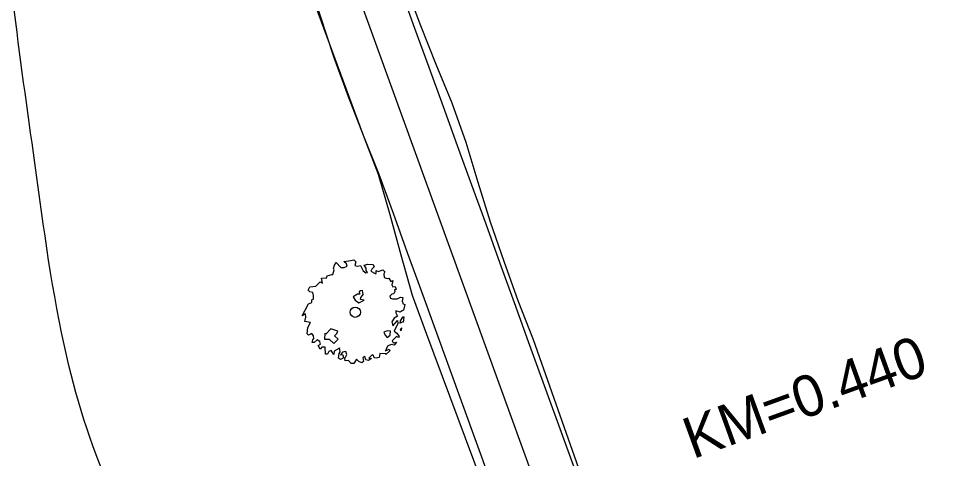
# Model space of a CAD drawing. Extents: x -475575 to -473225, y -1116053 to -1114104.
# Drawn here: x -474215.18 to -474170.87, y -1115076.88 to -1115055.77 of the extents above; entities that cross this region are included whole.
import ezdxf

# ---------------------------------------------------------------- set-up
doc = ezdxf.new("R2010")
doc.units = 0
for name, color, linetype in [('CESTN___P____KOP_N__VRH', 7, 'Continuous'), ('CESTN___P____KOP_N__VRH__Construction_', 7, 'Continuous'), ('IP', 7, 'Continuous'), ('POLYGONY_SITUACE_PF_POPISY', 7, 'Continuous'), ('POLYGONY_SITUACE_PO', 7, 'Continuous'), ('Vrstevnice_vedlejsi', 7, 'Continuous')]:
    doc.layers.add(name, color=color, linetype=linetype)

msp = doc.modelspace()

# ---------------------------------------------------------------- linework, layer by layer
at = {"layer": 'CESTN___P____KOP_N__VRH'}
msp.add_lwpolyline([(-474214.371, -1115044.57), (-474211.961, -1115044.624), (-474209.401, -1115045.159), (-474206.197, -1115046.957), (-474204.043, -1115049), (-474202.628, -1115051.043), (-474201.908, -1115052.531), (-474198.644, -1115061.375)], dxfattribs=at)
at = {"layer": 'CESTN___P____KOP_N__VRH__Construction_'}
for p, q in [((-474199.594, -1115046.827), (-474196.185, -1115056.228)), ((-474195.889, -1115056.121), (-474199.382, -1115046.751)), ((-474195.147, -1115057.979), (-474195.889, -1115056.121)), ((-474196.185, -1115056.228), (-474195.503, -1115058.108)), ((-474200.065, -1115057.635), (-474199.368, -1115059.51)), ((-474195.503, -1115058.108), (-474194.821, -1115059.989)), ((-474194.377, -1115059.828), (-474195.147, -1115057.979)), ((-474199.368, -1115059.51), (-474198.644, -1115061.375)), ((-474194.821, -1115059.989), (-474194.139, -1115061.869)), ((-474193.717, -1115061.716), (-474194.377, -1115059.828)), ((-474198.644, -1115061.375), (-474197.9, -1115063.232)), ((-474198.644, -1115061.375), (-474197.93, -1115063.243)), ((-474194.139, -1115061.869), (-474193.458, -1115063.749)), ((-474193.138, -1115063.633), (-474193.717, -1115061.716)), ((-474197.93, -1115063.243), (-474197.377, -1115065.17)), ((-474197.9, -1115063.232), (-474197.218, -1115065.113)), ((-474192.541, -1115065.544), (-474193.138, -1115063.633)), ((-474193.458, -1115063.749), (-474192.776, -1115065.629)), ((-474197.377, -1115065.17), (-474196.84, -1115067.103)), ((-474197.218, -1115065.113), (-474196.536, -1115066.993)), ((-474192.776, -1115065.629), (-474192.094, -1115067.509)), ((-474191.883, -1115067.433), (-474192.541, -1115065.544)), ((-474196.84, -1115067.103), (-474196.308, -1115069.037)), ((-474196.536, -1115066.993), (-474195.854, -1115068.873)), ((-474192.094, -1115067.509), (-474191.412, -1115069.39)), ((-474191.215, -1115069.318), (-474191.883, -1115067.433)), ((-474195.854, -1115068.873), (-474184.886, -1115099.122)), ((-474196.308, -1115069.037), (-474195.612, -1115070.912)), ((-474191.412, -1115069.39), (-474190.731, -1115071.27)), ((-474190.479, -1115071.179), (-474191.215, -1115069.318)), ((-474195.612, -1115070.912), (-474185.046, -1115099.18)), ((-474181.118, -1115097.755), (-474190.479, -1115071.179)), ((-474190.731, -1115071.27), (-474181.126, -1115097.758))]:
    msp.add_line(p, q, dxfattribs=at)
msp.add_lwpolyline([(-474203.734, -1115048.833), (-474202.08, -1115051.439), (-474200.065, -1115057.635)], dxfattribs=at)
at = {"layer": 'IP'}
for points in [[(-474197.058, -1115071.292), (-474197.172, -1115071.441), (-474197.301, -1115071.406), (-474197.477, -1115071.497), (-474197.573, -1115071.707), (-474197.402, -1115071.64), (-474197.378, -1115071.719), (-474197.571, -1115071.898), (-474197.56, -1115071.863), (-474197.856, -1115071.849), (-474197.876, -1115072.031), (-474198.006, -1115072.07), (-474198.124, -1115072.047), (-474198.148, -1115071.943), (-474198.219, -1115071.914), (-474198.372, -1115072.065), (-474198.248, -1115072.086), (-474198.391, -1115072.179), (-474198.525, -1115072.143), (-474198.575, -1115071.99), (-474198.669, -1115072.037), (-474198.627, -1115072.23), (-474198.72, -1115072.284), (-474198.857, -1115072.225), (-474198.97, -1115072.108), (-474199.099, -1115072.32), (-474199.221, -1115072.316), (-474199.351, -1115072.174), (-474199.506, -1115072.189), (-474199.529, -1115072.081), (-474199.438, -1115071.89), (-474199.487, -1115071.746), (-474199.646, -1115071.771), (-474199.73, -1115071.907), (-474199.646, -1115071.896), (-474199.608, -1115071.964), (-474199.59, -1115072.054), (-474199.743, -1115072.126), (-474199.832, -1115072.061), (-474199.802, -1115071.836), (-474199.751, -1115071.758), (-474199.778, -1115071.567), (-474199.786, -1115071.587), (-474200.035, -1115071.728), (-474200.056, -1115071.891), (-474200.179, -1115071.703), (-474200.3, -1115071.74), (-474200.356, -1115071.874), (-474200.454, -1115071.871), (-474200.47, -1115071.545), (-474200.63, -1115071.538), (-474200.707, -1115071.628), (-474200.801, -1115071.465), (-474200.7, -1115071.397), (-474200.732, -1115071.26), (-474200.855, -1115071.179), (-474201.003, -1115071.321), (-474201.09, -1115071.322), (-474201.07, -1115071.187), (-474201.024, -1115071.117), (-474201.029, -1115070.996), (-474201.112, -1115070.889), (-474201.271, -1115070.965), (-474201.332, -1115070.9), (-474201.299, -1115070.59), (-474201.177, -1115070.361), (-474201.447, -1115070.301), (-474201.392, -1115070.093), (-474201.409, -1115069.947), (-474201.577, -1115070.04), (-474201.278, -1115069.463), (-474201.116, -1115069.393), (-474201.11, -1115069.264), (-474201.035, -1115069.236), (-474201.031, -1115069.056), (-474201.058, -1115068.919), (-474201.215, -1115068.889), (-474201.285, -1115068.802), (-474201.205, -1115068.647), (-474200.921, -1115068.615), (-474200.719, -1115068.407), (-474200.608, -1115068.467), (-474200.652, -1115068.222), (-474200.407, -1115068.206), (-474200.38, -1115068.117), (-474200.156, -1115068.054), (-474200.103, -1115068.055), (-474200.04, -1115067.824), (-474200.078, -1115067.758), (-474200.02, -1115067.6), (-474199.939, -1115067.473), (-474199.729, -1115067.709), (-474199.563, -1115067.716), (-474199.42, -1115067.648), (-474199.455, -1115067.539), (-474199.583, -1115067.432), (-474199.344, -1115067.401), (-474199.097, -1115067.342), (-474199.01, -1115067.439), (-474199.051, -1115067.628), (-474198.928, -1115067.647), (-474198.777, -1115067.615), (-474198.644, -1115067.872), (-474198.529, -1115067.97), (-474198.435, -1115067.953), (-474198.512, -1115067.855), (-474198.512, -1115067.741), (-474198.596, -1115067.606), (-474198.422, -1115067.552), (-474198.169, -1115067.567), (-474198.121, -1115067.687), (-474198.241, -1115067.789), (-474198.281, -1115067.898), (-474198.071, -1115068.001), (-474198.035, -1115068.011), (-474198.033, -1115067.856), (-474197.915, -1115067.914), (-474197.842, -1115067.87), (-474197.712, -1115067.827), (-474197.61, -1115067.917), (-474197.654, -1115068.02), (-474197.637, -1115068.198), (-474197.498, -1115068.243), (-474197.412, -1115068.225), (-474197.325, -1115068.383), (-474197.231, -1115068.342), (-474197.274, -1115068.547), (-474197.222, -1115068.639), (-474197.118, -1115068.634), (-474197.073, -1115068.769), (-474197.143, -1115068.783), (-474197.137, -1115068.865), (-474197.163, -1115068.952), (-474197.201, -1115068.986), (-474197.268, -1115069.001), (-474197.327, -1115069.044), (-474197.369, -1115069.098), (-474197.345, -1115069.181), (-474197.246, -1115069.217), (-474197.025, -1115069.218), (-474196.855, -1115069.145), (-474196.75, -1115069.154), (-474196.781, -1115069.336), (-474196.736, -1115069.466), (-474196.658, -1115069.497), (-474196.719, -1115069.769), (-474196.787, -1115069.792), (-474196.883, -1115069.854), (-474197.08, -1115069.799), (-474197.088, -1115069.897), (-474197, -1115070.053), (-474197.158, -1115070.151), (-474197.268, -1115070.316), (-474197.225, -1115070.519), (-474197.002, -1115070.264), (-474196.99, -1115070.4), (-474197.167, -1115070.777), (-474197.032, -1115070.859), (-474196.932, -1115071.028), (-474196.952, -1115071.073), (-474197.056, -1115071.025), (-474197.26, -1115071.233), (-474197.216, -1115071.329)], [(-474198.787, -1115069), (-474198.93, -1115069), (-474199.131, -1115069.129), (-474199.035, -1115069.28), (-474198.86, -1115069.408), (-474198.6, -1115069.285), (-474198.776, -1115069.255), (-474198.758, -1115069.152), (-474198.688, -1115069.056), (-474198.658, -1115069.015), (-474198.68, -1115068.827), (-474198.774, -1115068.838), (-474198.85, -1115068.889), (-474198.821, -1115068.961)], [(-474196.767, -1115070.094), (-474196.879, -1115070.271), (-474196.894, -1115070.386), (-474196.74, -1115070.312), (-474196.716, -1115070.344), (-474196.681, -1115070.096)], [(-474199.871, -1115070.768), (-474200.199, -1115070.655), (-474200.44, -1115070.915), (-474200.493, -1115070.866), (-474200.5, -1115071.156), (-474200.28, -1115071.161), (-474200.058, -1115071.37), (-474199.849, -1115071.148), (-474200.019, -1115070.989), (-474199.921, -1115070.885)], [(-474197.347, -1115070.775), (-474197.503, -1115070.749), (-474197.654, -1115070.826), (-474197.602, -1115070.964), (-474197.498, -1115071.074), (-474197.361, -1115070.96)], [(-474196.8, -1115070.619), (-474196.879, -1115070.695), (-474196.841, -1115070.743), (-474196.807, -1115070.719)]]:
    msp.add_lwpolyline(points, close=True, dxfattribs=at)
msp.add_circle((-474199.027, -1115069.862), 0.247, dxfattribs=at)
at = {"layer": 'POLYGONY_SITUACE_PO'}
msp.add_lwpolyline([(-474033.93, -1115484.017), (-474028.81, -1115469.55), (-474027.706, -1115465.586), (-474027.155, -1115461.509), (-474027.167, -1115457.394), (-474027.702, -1115449.947), (-474028.133, -1115446.706), (-474028.952, -1115443.542), (-474030.148, -1115440.499), (-474155.776, -1115170.193), (-474159.336, -1115162.232), (-474162.663, -1115154.172), (-474165.754, -1115146.018), (-474287.504, -1114810.25), (-474291.915, -1114795.876)], dxfattribs=at)
at = {"layer": 'Vrstevnice_vedlejsi'}
for points in [[(-474198.341, -1114669.49), (-474196.681, -1114672.256), (-474195.18, -1114674.653), (-474193.836, -1114676.681), (-474192.651, -1114678.341), (-474192.443, -1114683.526), (-474193.214, -1114692.237), (-474194.962, -1114704.473), (-474196.31, -1114712.997), (-474197.258, -1114717.807), (-474197.807, -1114718.903), (-474198.355, -1114720.033), (-474198.903, -1114721.196), (-474199.452, -1114722.393), (-474202.29, -1114724.764), (-474207.417, -1114728.309), (-474214.834, -1114733.029), (-474221.352, -1114738.648), (-474226.971, -1114745.166), (-474231.691, -1114752.583), (-474235.037, -1114757.727), (-474237.009, -1114760.598), (-474237.607, -1114761.196), (-474238.205, -1114762.022), (-474238.804, -1114763.076), (-474239.402, -1114764.358), (-474242.028, -1114769.031), (-474246.681, -1114777.093), (-474253.362, -1114788.547), (-474258.559, -1114799.152), (-474262.27, -1114808.908), (-474264.497, -1114817.816), (-474266.676, -1114825.23), (-474268.807, -1114831.15), (-474270.889, -1114835.575), (-474272.278, -1114842.188), (-474272.972, -1114850.991), (-474272.972, -1114861.981), (-474273.054, -1114870.089), (-474273.218, -1114875.314), (-474273.465, -1114877.657), (-474273.273, -1114882.608), (-474272.641, -1114890.167), (-474271.571, -1114900.334), (-474271.061, -1114908.167), (-474271.11, -1114913.667), (-474271.719, -1114916.834), (-474271.646, -1114922.058), (-474270.891, -1114929.339), (-474269.454, -1114938.678), (-474268.091, -1114946.236), (-474266.802, -1114952.012), (-474265.586, -1114956.006), (-474264.292, -1114960.893), (-474262.92, -1114966.673), (-474261.469, -1114973.346), (-474259.897, -1114980.014), (-474258.202, -1114986.679), (-474256.386, -1114993.34), (-474254.916, -1115000.31), (-474253.793, -1115007.591), (-474253.017, -1115015.182), (-474252.121, -1115021.507), (-474251.104, -1115026.568), (-474249.968, -1115030.364), (-474249.22, -1115033.873), (-474248.86, -1115037.095), (-474248.889, -1115040.031), (-474248.926, -1115042.279), (-474248.97, -1115043.838), (-474249.022, -1115044.709), (-474249.185, -1115045.346), (-474249.46, -1115045.75), (-474249.845, -1115045.92), (-474250.053, -1115046.628), (-474250.085, -1115047.873), (-474249.939, -1115049.656), (-474250.24, -1115054.341), (-474250.987, -1115061.928), (-474252.18, -1115072.418), (-474252.552, -1115080.569), (-474252.103, -1115086.383), (-474250.833, -1115089.859), (-474248.888, -1115093.001), (-474246.267, -1115095.808), (-474242.971, -1115098.281), (-474237.53, -1115101.018), (-474229.942, -1115104.018), (-474220.207, -1115107.282), (-474212.554, -1115110.016), (-474206.982, -1115112.221), (-474203.491, -1115113.895), (-474200.507, -1115114.848), (-474198.031, -1115115.078), (-474196.062, -1115114.586), (-474193.634, -1115114.914), (-474190.746, -1115116.062)], [(-474106.724, -1115139.906), (-474105.975, -1115134.747), (-474104.91, -1115130.242), (-474103.528, -1115126.392), (-474101.829, -1115123.196), (-474101.248, -1115119.409), (-474101.786, -1115115.032), (-474103.442, -1115110.065), (-474106.201, -1115105.465), (-474110.065, -1115101.234), (-474115.032, -1115097.37), (-474120.595, -1115093.294), (-474126.753, -1115089.004), (-474133.506, -1115084.502), (-474139.856, -1115081.154), (-474145.801, -1115078.961), (-474151.342, -1115077.922), (-474155.382, -1115077.318), (-474157.922, -1115077.148), (-474158.961, -1115077.413), (-474159.927, -1115077.355), (-474160.82, -1115076.975), (-474161.64, -1115076.273), (-474163.375, -1115076.297), (-474166.027, -1115077.047), (-474169.593, -1115078.523), (-474174.953, -1115080.253), (-474182.107, -1115082.237), (-474191.053, -1115084.473), (-474198.277, -1115085.36), (-474203.777, -1115084.898), (-474207.554, -1115083.087), (-474210.582, -1115078.783), (-474212.862, -1115071.987), (-474214.394, -1115062.7), (-474215.425, -1115054.98), (-474215.955, -1115048.829), (-474215.985, -1115044.245), (-474215.583, -1115041.048), (-474214.749, -1115039.236), (-474213.484, -1115038.81), (-474212.393, -1115038.422), (-474211.477, -1115038.073), (-474210.736, -1115037.762), (-474210.235, -1115036.623), (-474209.974, -1115034.657), (-474209.953, -1115031.862), (-474210.087, -1115026.769), (-474210.376, -1115019.378), (-474210.819, -1115009.689), (-474212.181, -1114998.785), (-474214.462, -1114986.667), (-474217.662, -1114973.333), (-474220.697, -1114961.225), (-474223.567, -1114950.342), (-474226.271, -1114940.683), (-474228.65, -1114933.019), (-474230.705, -1114927.35), (-474232.434, -1114923.675), (-474233.1, -1114917.916), (-474232.704, -1114910.072), (-474231.244, -1114900.144), (-474229.766, -1114892.391), (-474228.27, -1114886.811), (-474226.756, -1114883.405), (-474225.554, -1114878.524), (-474224.663, -1114872.166), (-474224.082, -1114864.332), (-474222.871, -1114857.276), (-474221.027, -1114850.999), (-474218.553, -1114845.499), (-474216.392, -1114840.557), (-474214.547, -1114836.172), (-474213.015, -1114832.344), (-474210.719, -1114828.319), (-474207.656, -1114824.099), (-474203.828, -1114819.682), (-474200.394, -1114815.041), (-474197.354, -1114810.176), (-474194.708, -1114805.088), (-474192.13, -1114800), (-474189.62, -1114794.912), (-474187.178, -1114789.824), (-474182.801, -1114780.435), (-474176.49, -1114766.746), (-474168.245, -1114748.757), (-474162.295, -1114736.021), (-474158.639, -1114728.54), (-474157.277, -1114726.312), (-474156.001, -1114724.373), (-474154.81, -1114722.723), (-474153.704, -1114721.361), (-474151.414, -1114718.384), (-474147.941, -1114713.791), (-474143.284, -1114707.582), (-474139.388, -1114701.068), (-474136.252, -1114694.249)]]:
    msp.add_spline(points, degree=3, dxfattribs=at)

# ---------------------------------------------------------------- texts
at = {"layer": 'POLYGONY_SITUACE_PF_POPISY'}
msp.add_text('KM=0.440', height=1.9765, rotation=19.9307, dxfattribs=at).set_placement((-474182.844, -1115076.92))

doc.saveas('drawing.dxf')
